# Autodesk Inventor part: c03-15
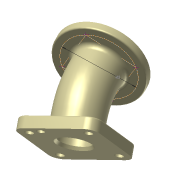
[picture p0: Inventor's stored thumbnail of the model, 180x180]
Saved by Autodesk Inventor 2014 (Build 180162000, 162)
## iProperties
Created: 2011-11
Part Number: c03-15
Material: Iron, Cast
Document SubType Name: Modeling
Designer: Thom Tremblay
Density: 7.25 g/cm^3
Mass: 1087.5 g
Surface Area: 260 cm^2
Volume: 150 cm^3
Appearance: Nylon 6
Author: Thom Tremblay
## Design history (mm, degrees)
sketch "Sketch1"
  geometry: L1 (50, -50)-(-50, -50); L2 (-50, -50)-(-50, 50); L3 (-50, 50)-(50, 50); L4 (50, 50)-(50, -50); C1 r 20 at (0, 0); C2 r 30 at (0, 0); 3 further points
  constraints: 8 end point, 2 centre point, 2 coincident, 2 midpoint, 2 parallel, 2 perpendicular, 1 horizontal, 1 horizontal alignment, 1 vertical alignment
  dimensions: "d0" = 100 distance of L2.end L3.end; "d3" = 40 diameter of C1; "d4" = 10 radial gap between concentric circles of C2 C1
extrude "Extrusion1" new body sketch "Sketch1" distance "d1" = 15; taper "d2" = 0 deg
sketch "Sketch2"
  geometry: L1 (0, 0)-(0, 30); L2 (12.794, 77.746)-(27.794, 103.727); A1 r 95.493 centre (95.493, 30) between (12.794, 77.746) and (0, 30)
  constraints: 4 end point, 2 point on circle, 2 tangent, 1 centre point, 1 vertical
  dimensions: "d5" = 30 distance of L1.start L1.end; "d7" = 50 dimension on A1; "d9" = 30 distance of L2.start L2.end; "d10" = 30 deg angle of L2 L1
sketch "Sketch3"
  geometry: L1 (12.794, 77.746)-(27.794, 103.727) reference; L2 (27.794, 103.727)-(75.425, 76.227); L3 (75.425, 76.227)-(70.425, 67.567); L4 (70.425, 67.567)-(22.794, 95.067); L5 (22.794, 95.067)-(27.794, 103.727); 2 further points
  constraints: 8 end point, 2 parallel, 2 perpendicular
  dimensions: "d11" = 110 diameter of L3 L5; "d13" = 10 distance between parallel lines of L2 L4
revolve "Revolution1" sketch "Sketch3" stored, may be unused: angle "d14" = 90 deg
sweep "Sweep1" dims "d15" = 0
sweep "Sweep2" dims "d16" = 0
sketch "Sketch4"
  geometry: C1 r 55 at (0, 0) reference; C2 r 27.5 at (0, 0); 1 further point
  constraints: 1 centre point, 1 coincident
  dimensions: "d17" = 55 diameter of C2
extrude "Extrusion2" cut sketch "Sketch4" distance "d18" = 5; taper "d19" = 0 deg
fillet "Fillet1" dims "d20" = 14
fillet "Fillet2" dims "d21" = 6, "d22" = 2
chamfer "Chamfer1" distance "d23" = 2; stored, may be unused: second distance "d24" = 2, angle "d25" = 45 deg
chamfer "Chamfer2" distance "d26" = 2; stored, may be unused: second distance "d27" = 4, angle "d28" = 45 deg
hole "Hole1" diameter "d31" = 10; stored, may be unused: countersink angle "d35" = 90 deg, drill point angle "d37" = 118 deg; dims "d32" = 6, "d33" = 15, "d34" = 9, "d36" = 8, "d69" = 30, "d70" = 10
hole "Hole5" diameter "d73" = 11; stored, may be unused: countersink angle "d77" = 90 deg, drill point angle "d79" = 118 deg; dims "d71" = 10, "d72" = 10, "d74" = 6, "d75" = 20, "d76" = 2, "d78" = 8
pattern_circular "Circular Pattern1" dims angle "d39" = 360 deg
sketch "Sketch5" dims "d41" = 90
  geometry: L1 (0, 45)-(45, 0); L2 (45, 0)-(0, -45); L3 (0, -45)-(-45, 0); L4 (-45, 0)-(0, 45); C1 r 31.235 at (0, 0); 3 further points
  constraints: 8 end point, 2 coincident, 1 centre point, 1 vertical alignment, 11 other
body "Solid1"
